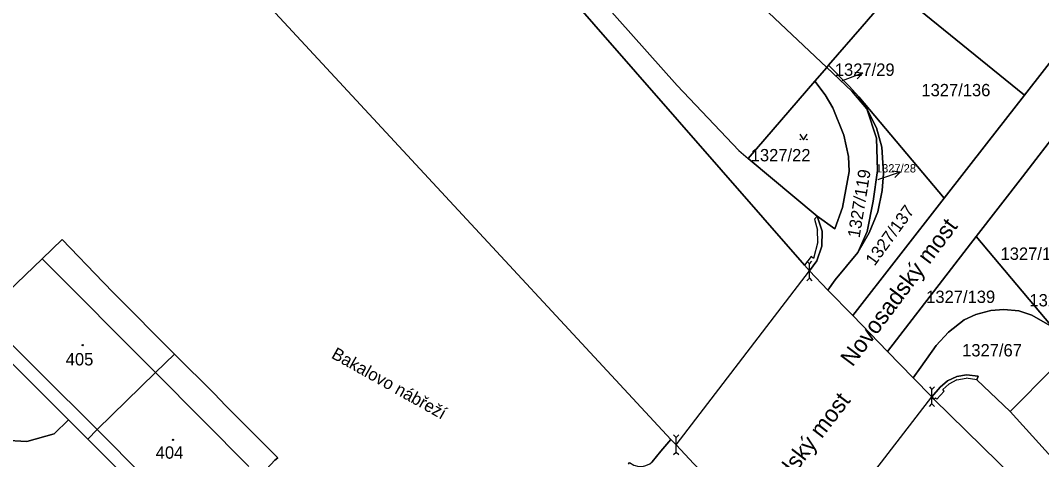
# Model space of a CAD drawing. Extents: x -598934 to -598196, y -1162208 to -1161502.
# Drawn here: x -598826.6 to -598686.2, y -1161928.6 to -1161868.2 of the extents above; entities that cross this region are included whole.
import ezdxf

# ---------------------------------------------------------------- set-up
doc = ezdxf.new("R2010")
doc.units = 0
for name, color, linetype in [('KN_CAR_KR', 7, 'Continuous'), ('KN_KULTURY', 7, 'Continuous'), ('KN_PARC_CIS_POM', 7, 'Continuous'), ('KN_PARC_CIS_POZ', 7, 'Continuous'), ('KN_PARC_CIS_STAV', 7, 'Continuous'), ('KN_PARC_PLOCHA', 7, 'Continuous'), ('KN_ULICE', 7, 'Continuous'), ('PARC_C_SIPKA', 7, 'Continuous'), ('parcely_l', 7, 'Continuous')]:
    doc.layers.add(name, color=color, linetype=linetype)

msp = doc.modelspace()

# ---------------------------------------------------------------- linework, layer by layer
at = {"layer": 'KN_CAR_KR'}
for points in [[(-598758.76, -1161851.79), (-598736.3, -1161877.12)], [(-598736.3, -1161877.12), (-598727.82, -1161886.06)], [(-598727.82, -1161886.06), (-598726.52, -1161887.16)], [(-598717.06, -1161895.1), (-598717.39, -1161895.49)], [(-598717.39, -1161895.49), (-598716.99, -1161897.03)], [(-598716.93, -1161898.6), (-598716.99, -1161897.03)], [(-598716.93, -1161898.6), (-598717.52, -1161900.92)], [(-598823.59, -1161900.97), (-598807.99, -1161916.61)], [(-598717.85, -1161900.66), (-598718.78, -1161901.85)], [(-598717.52, -1161900.92), (-598717.85, -1161900.66)], [(-598736.42, -1161926.53), (-598718.11, -1161902.63)], [(-598816.02, -1161924.42), (-598831.75, -1161908.81)], [(-598807.99, -1161916.61), (-598795.14, -1161929.52)], [(-598697.84, -1161917.6), (-598698.93, -1161918.18)], [(-598697.84, -1161917.6), (-598696.54, -1161917.37)], [(-598695.11, -1161917.58), (-598696.54, -1161917.37)], [(-598700.58, -1161920.27), (-598699.56, -1161919.17)], [(-598699.75, -1161918.93), (-598698.93, -1161918.18)], [(-598699.56, -1161919.17), (-598699.75, -1161918.93)], [(-598719.75, -1161943.9), (-598701.26, -1161919.92)], [(-598700.98, -1161920.26), (-598700.79, -1161920.07)], [(-598700.79, -1161920.07), (-598700.58, -1161920.27)], [(-598682.64, -1161930.66), (-598690.51, -1161921.94)], [(-598803.21, -1161937.3), (-598816.02, -1161924.42)]]:
    msp.add_lwpolyline(points, dxfattribs=at)
at = {"layer": 'KN_KULTURY'}
for p, q in [((-598718.11, -1161903.63), (-598718.11, -1161901.63)), ((-598701.26, -1161920.92), (-598701.26, -1161918.92)), ((-598736.42, -1161927.53), (-598736.42, -1161925.53))]:
    msp.add_line(p, q, dxfattribs=at)
for points in [[(-598719.4, -1161883.83), (-598718.9, -1161884.58), (-598718.4, -1161883.83)], [(-598718.46, -1161901.28), (-598718.11, -1161901.63), (-598717.76, -1161901.28)], [(-598718.46, -1161903.98), (-598718.11, -1161903.63), (-598717.76, -1161903.98)], [(-598701.61, -1161918.57), (-598701.26, -1161918.92), (-598700.91, -1161918.57)], [(-598701.61, -1161921.27), (-598701.26, -1161920.92), (-598700.91, -1161921.27)], [(-598736.77, -1161925.18), (-598736.42, -1161925.53), (-598736.07, -1161925.18)], [(-598736.77, -1161927.88), (-598736.42, -1161927.53), (-598736.07, -1161927.88)]]:
    msp.add_lwpolyline(points, dxfattribs=at)
for centre, radius in [((-598719.35, -1161884.53), 0.05), ((-598718.45, -1161884.53), 0.05), ((-598817.99, -1161912.83), 0.09), ((-598817.99, -1161912.83), 0.0398), ((-598805.59, -1161925.85), 0.09), ((-598805.59, -1161925.85), 0.0398)]:
    msp.add_circle(centre, radius, dxfattribs=at)
at = {"layer": 'KN_PARC_PLOCHA'}
for points in [[(-598706.46, -1161863.86), (-598710.87, -1161868.99), (-598715.47, -1161874.34), (-598715.73, -1161874.64), (-598750.92, -1161841.39), (-598756.72, -1161836.11), (-598757.85, -1161834.68), (-598759.43, -1161832.13), (-598774.72, -1161817.99), (-598790.05, -1161803.84), (-598820.04, -1161776.24), (-598815.82, -1161772.05), (-598809.07, -1161765.33), (-598810.35, -1161768.53), (-598807.67, -1161770.87), (-598788.32, -1161789.06), (-598775.14, -1161801.38), (-598747.17, -1161827.01), (-598709.53, -1161861.91)], [(-598715.73, -1161874.64), (-598717.35, -1161876.52), (-598726.52, -1161887.16), (-598717.06, -1161895.1), (-598716.37, -1161897.16), (-598716.4, -1161899.22), (-598717.1, -1161901.24), (-598718.11, -1161902.63), (-598718.78, -1161901.85), (-598788.14, -1161822.37), (-598808.06, -1161799.42), (-598821.65, -1161784.92), (-598825.17, -1161781.28), (-598823.72, -1161779.88), (-598820.04, -1161776.24), (-598790.05, -1161803.84), (-598774.72, -1161817.99), (-598759.43, -1161832.13), (-598757.85, -1161834.68), (-598756.72, -1161836.11), (-598750.92, -1161841.39)], [(-598688.55, -1161878.47), (-598693.74, -1161885.15), (-598699.57, -1161892.63), (-598711.3, -1161878.68), (-598712.66, -1161877.19), (-598715.47, -1161874.34), (-598710.87, -1161868.99), (-598706.46, -1161863.86)], [(-598711.3, -1161878.68), (-598710.2, -1161880.33), (-598712.27, -1161877.91), (-598715.73, -1161874.64), (-598715.47, -1161874.34), (-598712.66, -1161877.19)], [(-598710.2, -1161880.33), (-598708.88, -1161884.35), (-598708.73, -1161888.83), (-598709.34, -1161893.03), (-598710.15, -1161897.2), (-598711.46, -1161900.11), (-598714.55, -1161903.84), (-598715.55, -1161905.25), (-598718.11, -1161902.63), (-598717.1, -1161901.24), (-598716.4, -1161899.22), (-598716.37, -1161897.16), (-598717.06, -1161895.1), (-598714.6, -1161896.81), (-598713.57, -1161893.92), (-598712.62, -1161888.93), (-598712.73, -1161886.87), (-598713.37, -1161883.93), (-598714.88, -1161880.2), (-598715.92, -1161878.41), (-598717.35, -1161876.52), (-598715.73, -1161874.64), (-598712.27, -1161877.91)], [(-598717.06, -1161895.1), (-598726.52, -1161887.16), (-598717.35, -1161876.52), (-598715.92, -1161878.41), (-598714.88, -1161880.2), (-598713.37, -1161883.93), (-598712.73, -1161886.87), (-598712.62, -1161888.93), (-598713.57, -1161893.92), (-598714.6, -1161896.81)], [(-598699.57, -1161892.63), (-598712.14, -1161908.77), (-598715.55, -1161905.25), (-598714.55, -1161903.84), (-598711.46, -1161900.11), (-598709.91, -1161897.38), (-598708.7, -1161894.48), (-598708.08, -1161891.57), (-598707.9, -1161889.22), (-598708.16, -1161885.58), (-598708.87, -1161882.94), (-598710.2, -1161880.33), (-598711.3, -1161878.68)], [(-598711.46, -1161900.11), (-598710.15, -1161897.2), (-598709.34, -1161893.03), (-598708.73, -1161888.83), (-598708.88, -1161884.35), (-598710.2, -1161880.33), (-598708.87, -1161882.94), (-598708.16, -1161885.58), (-598707.9, -1161889.22), (-598708.08, -1161891.57), (-598708.7, -1161894.48), (-598709.91, -1161897.38)], [(-598670.57, -1161893.33), (-598669.8, -1161896.31), (-598667.72, -1161899.35), (-598669.24, -1161900.87), (-598672.85, -1161904.41), (-598677.88, -1161909.36), (-598680.13, -1161909.46), (-598682.02, -1161909.99), (-598683.3, -1161910.59), (-598684, -1161911.17), (-598695.16, -1161897.89), (-598688.82, -1161889.68), (-598683.43, -1161882.7)], [(-598684, -1161911.17), (-598685.05, -1161910.11), (-598687.53, -1161908.7), (-598689.32, -1161908.13), (-598691.38, -1161907.92), (-598693.18, -1161908.07), (-598695.22, -1161908.62), (-598696.83, -1161909.36), (-598699, -1161911.05), (-598700.66, -1161912.89), (-598702.8, -1161915.85), (-598703.84, -1161917.32), (-598707.37, -1161913.69), (-598695.16, -1161897.89)], [(-598805.37, -1161914.05), (-598807.99, -1161916.61), (-598816.02, -1161924.42), (-598817.27, -1161925.78), (-598819.97, -1161923.09), (-598833.05, -1161910.04), (-598831.75, -1161908.81), (-598831.33, -1161908.4), (-598831.77, -1161907.95), (-598834.38, -1161905.37), (-598834.92, -1161904.74), (-598834.52, -1161904.36), (-598832.1, -1161902.27), (-598831.74, -1161901.81), (-598831.31, -1161902.35), (-598828.26, -1161905.43), (-598823.59, -1161900.97), (-598820.83, -1161898.32), (-598815.19, -1161904.19), (-598813.72, -1161905.68)], [(-598684, -1161911.17), (-598684.33, -1161911.44), (-598683.21, -1161912.1), (-598681.87, -1161913.33), (-598684.58, -1161916.02), (-598690.51, -1161921.94), (-598695.11, -1161917.58), (-598694.89, -1161917.09), (-598696.49, -1161916.92), (-598697.85, -1161917.15), (-598699.11, -1161917.76), (-598700.12, -1161918.59), (-598701.26, -1161919.92), (-598703.84, -1161917.32), (-598702.8, -1161915.85), (-598700.66, -1161912.89), (-598699, -1161911.05), (-598696.83, -1161909.36), (-598695.22, -1161908.62), (-598693.18, -1161908.07), (-598691.38, -1161907.92), (-598689.32, -1161908.13), (-598687.53, -1161908.7), (-598685.05, -1161910.11)], [(-598819.97, -1161923.09), (-598821.92, -1161925.02), (-598825.66, -1161926.09), (-598828.95, -1161925.89), (-598833.7, -1161923.04), (-598835.93, -1161918.91), (-598835.4, -1161912.6), (-598833.05, -1161910.04)], [(-598791.6, -1161928.67), (-598793.94, -1161931.18), (-598799.64, -1161940.73), (-598800.34, -1161940.54), (-598801.08, -1161940.48), (-598803.2, -1161939.89), (-598817.27, -1161925.78), (-598816.02, -1161924.42), (-598807.99, -1161916.61), (-598805.37, -1161914.05), (-598799.89, -1161919.53), (-598798.35, -1161921.13), (-598791.18, -1161928.31)]]:
    msp.add_lwpolyline(points, close=True, dxfattribs=at)
for points in [[(-598680.91, -1161868.67), (-598688.55, -1161878.47), (-598706.46, -1161863.86), (-598706.17, -1161863.52), (-598704.76, -1161864.56), (-598702.84, -1161865.23), (-598699.9, -1161865.71), (-598696.84, -1161865.63), (-598694.88, -1161865.24), (-598693.01, -1161864.55), (-598691.19, -1161863.64), (-598689.5, -1161862.53), (-598687.63, -1161860.84), (-598686.85, -1161859.98), (-598651.94, -1161817.27)], [(-598788.14, -1161822.37), (-598718.78, -1161901.85), (-598718.11, -1161902.63), (-598715.55, -1161905.25), (-598712.14, -1161908.77), (-598707.37, -1161913.69), (-598703.84, -1161917.32), (-598701.26, -1161919.92), (-598700.98, -1161920.26), (-598681.1, -1161939.74)], [(-598813.1, -1161843.8), (-598737.15, -1161925.8), (-598738.52, -1161927.42), (-598739.72, -1161928.9)], [(-598667.16, -1161993.18), (-598693.35, -1161970.89), (-598708.28, -1161956.21), (-598714.8, -1161949.33), (-598719.01, -1161944.61), (-598719.41, -1161944.16), (-598719.75, -1161943.9), (-598722.36, -1161941.17), (-598725.15, -1161938.28), (-598731.03, -1161932.2), (-598733.97, -1161929.15), (-598736.42, -1161926.53), (-598737.15, -1161925.8), (-598813.1, -1161843.8)], [(-598683.43, -1161882.7), (-598688.82, -1161889.68), (-598695.16, -1161897.89), (-598707.37, -1161913.69), (-598712.14, -1161908.77), (-598699.57, -1161892.63), (-598693.74, -1161885.15), (-598688.55, -1161878.47), (-598680.91, -1161868.67)], [(-598791.6, -1161928.67), (-598791.18, -1161928.31), (-598798.35, -1161921.13), (-598799.89, -1161919.53), (-598805.37, -1161914.05), (-598813.72, -1161905.68), (-598815.19, -1161904.19), (-598820.83, -1161898.32), (-598823.59, -1161900.97), (-598828.26, -1161905.43)], [(-598681.1, -1161939.74), (-598700.98, -1161920.26), (-598701.26, -1161919.92), (-598700.12, -1161918.59), (-598699.11, -1161917.76), (-598697.85, -1161917.15), (-598696.49, -1161916.92), (-598694.89, -1161917.09), (-598695.11, -1161917.58), (-598690.51, -1161921.94), (-598684.58, -1161916.02)], [(-598828.95, -1161925.89), (-598825.66, -1161926.09), (-598821.92, -1161925.02), (-598819.97, -1161923.09), (-598817.27, -1161925.78), (-598803.2, -1161939.89)], [(-598739.72, -1161928.9), (-598738.52, -1161927.42), (-598737.15, -1161925.8), (-598736.42, -1161926.53), (-598733.97, -1161929.15)]]:
    msp.add_lwpolyline(points, dxfattribs=at)
at = {"layer": 'PARC_C_SIPKA'}
for points in [[(-598713.6, -1161876.45), (-598713.57, -1161876.45), (-598710.77, -1161875.38)], [(-598711.88, -1161875.27), (-598710.77, -1161875.38), (-598711.52, -1161876.2)], [(-598708.67, -1161890.06), (-598708.43, -1161889.97), (-598705.6, -1161888.98)], [(-598706.71, -1161888.84), (-598705.6, -1161888.98), (-598706.38, -1161889.78)]]:
    msp.add_lwpolyline(points, dxfattribs=at)
at = {"layer": 'parcely_l'}
for points in [[(-598820.04, -1161776.24), (-598790.05, -1161803.84), (-598774.72, -1161817.99), (-598759.43, -1161832.13), (-598757.85, -1161834.68), (-598756.72, -1161836.11), (-598750.92, -1161841.39), (-598715.73, -1161874.64)], [(-598825.17, -1161781.28), (-598821.65, -1161784.92), (-598808.06, -1161799.42), (-598788.14, -1161822.37), (-598718.78, -1161901.85), (-598718.11, -1161902.63)], [(-598737.15, -1161925.8), (-598813.1, -1161843.8), (-598846.83, -1161807.87), (-598870.15, -1161785.99)], [(-598715.47, -1161874.34), (-598710.87, -1161868.99), (-598706.46, -1161863.86)], [(-598706.46, -1161863.86), (-598688.55, -1161878.47)], [(-598688.55, -1161878.47), (-598680.91, -1161868.67)], [(-598715.73, -1161874.64), (-598715.47, -1161874.34)], [(-598711.3, -1161878.68), (-598712.66, -1161877.19), (-598715.47, -1161874.34)], [(-598715.73, -1161874.64), (-598717.35, -1161876.52)], [(-598715.73, -1161874.64), (-598712.27, -1161877.91), (-598710.2, -1161880.33)], [(-598717.35, -1161876.52), (-598726.52, -1161887.16), (-598717.06, -1161895.1)], [(-598717.06, -1161895.1), (-598714.6, -1161896.81), (-598713.57, -1161893.92), (-598712.62, -1161888.93), (-598712.73, -1161886.87), (-598713.37, -1161883.93), (-598714.88, -1161880.2), (-598715.92, -1161878.41), (-598717.35, -1161876.52)], [(-598699.57, -1161892.63), (-598693.74, -1161885.15), (-598688.55, -1161878.47)], [(-598699.57, -1161892.63), (-598711.3, -1161878.68)], [(-598710.2, -1161880.33), (-598711.3, -1161878.68)], [(-598711.46, -1161900.11), (-598710.15, -1161897.2), (-598709.34, -1161893.03), (-598708.73, -1161888.83), (-598708.88, -1161884.35), (-598710.2, -1161880.33)], [(-598710.2, -1161880.33), (-598708.87, -1161882.94), (-598708.16, -1161885.58), (-598707.9, -1161889.22), (-598708.08, -1161891.57), (-598708.7, -1161894.48), (-598709.91, -1161897.38), (-598711.46, -1161900.11)], [(-598695.16, -1161897.89), (-598688.82, -1161889.68), (-598683.43, -1161882.7)], [(-598712.14, -1161908.77), (-598699.57, -1161892.63)], [(-598717.06, -1161895.1), (-598716.37, -1161897.16), (-598716.4, -1161899.22), (-598717.1, -1161901.24), (-598718.11, -1161902.63)], [(-598707.37, -1161913.69), (-598695.16, -1161897.89)], [(-598684, -1161911.17), (-598695.16, -1161897.89)], [(-598831.74, -1161901.81), (-598831.31, -1161902.35), (-598828.26, -1161905.43), (-598823.59, -1161900.97), (-598820.83, -1161898.32), (-598815.19, -1161904.19), (-598813.72, -1161905.68), (-598805.37, -1161914.05)], [(-598711.46, -1161900.11), (-598714.55, -1161903.84), (-598715.55, -1161905.25)], [(-598718.11, -1161902.63), (-598715.55, -1161905.25)], [(-598715.55, -1161905.25), (-598712.14, -1161908.77)], [(-598684, -1161911.17), (-598685.05, -1161910.11), (-598687.53, -1161908.7), (-598689.32, -1161908.13), (-598691.38, -1161907.92), (-598693.18, -1161908.07), (-598695.22, -1161908.62), (-598696.83, -1161909.36), (-598699, -1161911.05), (-598700.66, -1161912.89), (-598702.8, -1161915.85), (-598703.84, -1161917.32)], [(-598712.14, -1161908.77), (-598707.37, -1161913.69)], [(-598819.97, -1161923.09), (-598821.92, -1161925.02), (-598825.66, -1161926.09), (-598828.95, -1161925.89), (-598833.7, -1161923.04), (-598835.93, -1161918.91), (-598835.4, -1161912.6), (-598833.05, -1161910.04)], [(-598819.97, -1161923.09), (-598833.05, -1161910.04)], [(-598703.84, -1161917.32), (-598707.37, -1161913.69)], [(-598805.37, -1161914.05), (-598807.99, -1161916.61), (-598816.02, -1161924.42), (-598817.27, -1161925.78)], [(-598805.37, -1161914.05), (-598799.89, -1161919.53), (-598798.35, -1161921.13), (-598791.18, -1161928.31), (-598791.6, -1161928.67)], [(-598701.26, -1161919.92), (-598700.12, -1161918.59), (-598699.11, -1161917.76), (-598697.85, -1161917.15), (-598696.49, -1161916.92), (-598694.89, -1161917.09), (-598695.11, -1161917.58), (-598690.51, -1161921.94), (-598684.58, -1161916.02)], [(-598703.84, -1161917.32), (-598701.26, -1161919.92)], [(-598701.26, -1161919.92), (-598700.98, -1161920.26), (-598681.1, -1161939.74), (-598658.35, -1161959.86), (-598630.16, -1161981.32), (-598613.97, -1161991.76), (-598595.97, -1162001.6), (-598578.01, -1162010.1), (-598568.51, -1162013.74)], [(-598817.27, -1161925.78), (-598819.97, -1161923.09)], [(-598817.27, -1161925.78), (-598803.2, -1161939.89)], [(-598742.99, -1161929.21), (-598742.84, -1161928.96), (-598742.22, -1161929.33), (-598741.54, -1161929.51), (-598741.06, -1161929.5), (-598740.57, -1161929.39), (-598740.06, -1161929.16), (-598739.72, -1161928.9), (-598738.52, -1161927.42), (-598737.15, -1161925.8)], [(-598737.15, -1161925.8), (-598736.42, -1161926.53), (-598733.97, -1161929.15), (-598731.03, -1161932.2)]]:
    msp.add_lwpolyline(points, dxfattribs=at)

# ---------------------------------------------------------------- texts
at = {"layer": 'KN_PARC_CIS_POM'}
for s, p in [('1327/29', (-598713.93, -1161876.45)), ('1327/28', (-598709, -1161890.06))]:
    msp.add_text(s, height=0.1, dxfattribs=at).set_placement(p)
at = {"layer": 'KN_PARC_CIS_POZ'}
for s, height, p in [('1327/29', 1.7, (-598714.61, -1161875.79)), ('1327/136', 1.7, (-598702.71, -1161878.6)), ('1327/22', 1.7, (-598726.17, -1161887.55)), ('1327/28', 1.14, (-598708.96, -1161889.08)), ('1327/138', 1.7, (-598691.83, -1161901.1)), ('1327/139', 1.7, (-598702.05, -1161907.03)), ('1327/21', 1.7, (-598687.86, -1161907.5)), ('1327/67', 1.7, (-598697.11, -1161914.38))]:
    msp.add_text(s, height=height, dxfattribs=at).set_placement(p)
for s, rotation, p in [('1327/119', 80.6036, (-598711.21, -1161898.16)), ('1327/137', 54, (-598709.15, -1161902.04))]:
    msp.add_text(s, height=1.7, rotation=rotation, dxfattribs=at).set_placement(p)
at = {"layer": 'KN_PARC_CIS_STAV'}
for s, p in [('405', (-598820.33, -1161915.62)), ('404', (-598807.96, -1161928.45))]:
    msp.add_text(s, height=1.7, dxfattribs=at).set_placement(p)
at = {"layer": 'KN_ULICE'}
for s, height, rotation, p in [('Novosadský most', 2.3, 53.1576, (-598712.18, -1161915.92)), ('Bakalovo nábřeží', 1.7, 330.7756, (-598783.94, -1161914.53)), ('Novosadský most', 2.3, 52.4881, (-598727.14, -1161939.73))]:
    msp.add_text(s, height=height, rotation=rotation, dxfattribs=at).set_placement(p)

doc.saveas('drawing.dxf')
